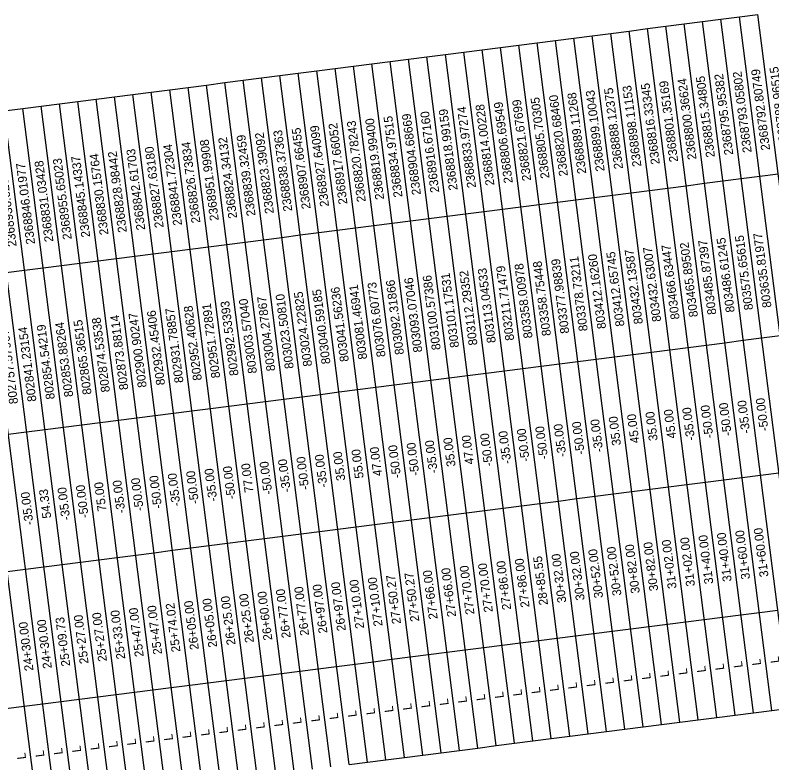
# Model space of a CAD drawing. Extents: x 2364621 to 2374814, y 792603 to 806745.
# Drawn here: x 2368280 to 2370303, y 801237 to 803235 of the extents above; entities that cross this region are included whole.
import ezdxf

# ---------------------------------------------------------------- set-up
doc = ezdxf.new("R2010")
doc.units = 0
doc.layers.add('CTL Sheet Table Cell', color=7, linetype='Continuous')
doc.layers.add('CTL Sheet Text', color=7, linetype='Continuous')

msp = doc.modelspace()

# ---------------------------------------------------------------- linework, layer by layer
at = {"layer": 'CTL Sheet Table Cell'}
for p, q in [((2370068.3, 803211.1), (2370117.4, 803217.4)), ((2370117.4, 803217.4), (2370166.5, 803223.7)), ((2370351.6, 801383.6), (2370117.4, 803217.4)), ((2370166.5, 803223.7), (2370215.7, 803229.9)), ((2370400.7, 801389.9), (2370166.5, 803223.7)), ((2370215.7, 803229.9), (2370264.8, 803236.2)), ((2370449.9, 801396.2), (2370215.7, 803229.9)), ((2370499, 801402.5), (2370264.8, 803236.2)), ((2369921, 803192.3), (2369970.1, 803198.6)), ((2369970.1, 803198.6), (2370019.2, 803204.8)), ((2370204.3, 801364.8), (2369970.1, 803198.6)), ((2370019.2, 803204.8), (2370068.3, 803211.1)), ((2370253.4, 801371.1), (2370019.2, 803204.8)), ((2370302.5, 801377.4), (2370068.3, 803211.1)), ((2369773.6, 803173.5), (2369822.7, 803179.7)), ((2369822.7, 803179.7), (2369871.8, 803186)), ((2370056.9, 801346), (2369822.7, 803179.7)), ((2369871.8, 803186), (2369921, 803192.3)), ((2370106, 801352.3), (2369871.8, 803186)), ((2370155.2, 801358.6), (2369921, 803192.3)), ((2369626.2, 803154.7), (2369675.4, 803160.9)), ((2369675.4, 803160.9), (2369724.5, 803167.2)), ((2369909.6, 801327.2), (2369675.4, 803160.9)), ((2369724.5, 803167.2), (2369773.6, 803173.5)), ((2369958.7, 801333.5), (2369724.5, 803167.2)), ((2370007.8, 801339.7), (2369773.6, 803173.5)), ((2369478.9, 803135.8), (2369528, 803142.1)), ((2369528, 803142.1), (2369577.1, 803148.4)), ((2369762.2, 801308.4), (2369528, 803142.1)), ((2369577.1, 803148.4), (2369626.2, 803154.7)), ((2369811.3, 801314.6), (2369577.1, 803148.4)), ((2369860.5, 801320.9), (2369626.2, 803154.7)), ((2369282.4, 803110.7), (2369331.5, 803117)), ((2369331.5, 803117), (2369380.7, 803123.3)), ((2369565.7, 801283.3), (2369331.5, 803117)), ((2369380.7, 803123.3), (2369429.8, 803129.6)), ((2369614.9, 801289.5), (2369380.7, 803123.3)), ((2369429.8, 803129.6), (2369478.9, 803135.8)), ((2369664, 801295.8), (2369429.8, 803129.6)), ((2369713.1, 801302.1), (2369478.9, 803135.8)), ((2369135.1, 803091.9), (2369184.2, 803098.2)), ((2369184.2, 803098.2), (2369233.3, 803104.5)), ((2369418.4, 801264.5), (2369184.2, 803098.2)), ((2369233.3, 803104.5), (2369282.4, 803110.7)), ((2369467.5, 801270.7), (2369233.3, 803104.5)), ((2369516.6, 801277), (2369282.4, 803110.7)), ((2368987.7, 803073.1), (2369036.8, 803079.4)), ((2369036.8, 803079.4), (2369086, 803085.6)), ((2369271, 801245.6), (2369036.8, 803079.4)), ((2369086, 803085.6), (2369135.1, 803091.9)), ((2369320.2, 801251.9), (2369086, 803085.6)), ((2369369.3, 801258.2), (2369135.1, 803091.9)), ((2368840.4, 803054.3), (2368889.5, 803060.6)), ((2368889.5, 803060.6), (2368938.6, 803066.8)), ((2369123.7, 801226.8), (2368889.5, 803060.6)), ((2368938.6, 803066.8), (2368987.7, 803073.1)), ((2369172.8, 801233.1), (2368938.6, 803066.8)), ((2369221.9, 801239.4), (2368987.7, 803073.1)), ((2368643.9, 803029.2), (2368693, 803035.5)), ((2368693, 803035.5), (2368742.1, 803041.7)), ((2368927.2, 801201.7), (2368693, 803035.5)), ((2368742.1, 803041.7), (2368791.2, 803048)), ((2368976.3, 801208), (2368742.1, 803041.7)), ((2368791.2, 803048), (2368840.4, 803054.3)), ((2369025.4, 801214.3), (2368791.2, 803048)), ((2369074.6, 801220.5), (2368840.4, 803054.3)), ((2368496.5, 803010.4), (2368545.7, 803016.6)), ((2368545.7, 803016.6), (2368594.8, 803022.9)), ((2368779.9, 801182.9), (2368545.7, 803016.6)), ((2368594.8, 803022.9), (2368643.9, 803029.2)), ((2368829, 801189.2), (2368594.8, 803022.9)), ((2368878.1, 801195.4), (2368643.9, 803029.2)), ((2368349.2, 802991.5), (2368398.3, 802997.8)), ((2368398.3, 802997.8), (2368447.4, 803004.1)), ((2368632.5, 801164.1), (2368398.3, 802997.8)), ((2368447.4, 803004.1), (2368496.5, 803010.4)), ((2368681.6, 801170.4), (2368447.4, 803004.1)), ((2368730.7, 801176.6), (2368496.5, 803010.4)), ((2368250.9, 802979), (2368300.1, 802985.3)), ((2368485.1, 801145.3), (2368250.9, 802979)), ((2368300.1, 802985.3), (2368349.2, 802991.5)), ((2368534.3, 801151.5), (2368300.1, 802985.3)), ((2368583.4, 801157.8), (2368349.2, 802991.5)), ((2368337.8, 801126.4), (2368103.6, 802960.2)), ((2368386.9, 801132.7), (2368152.7, 802966.5)), ((2368436, 801139), (2368201.8, 802972.7)), ((2370171.8, 802791.7), (2370220.9, 802798)), ((2370220.9, 802798), (2370270, 802804.2)), ((2370270, 802804.2), (2370319.1, 802810.5)), ((2369975.3, 802766.6), (2370024.4, 802772.9)), ((2370024.4, 802772.9), (2370073.6, 802779.1)), ((2370073.6, 802779.1), (2370122.7, 802785.4)), ((2370122.7, 802785.4), (2370171.8, 802791.7)), ((2369828, 802747.8), (2369877.1, 802754.1)), ((2369877.1, 802754.1), (2369926.2, 802760.3)), ((2369926.2, 802760.3), (2369975.3, 802766.6)), ((2369680.6, 802729), (2369729.7, 802735.2)), ((2369729.7, 802735.2), (2369778.9, 802741.5)), ((2369778.9, 802741.5), (2369828, 802747.8)), ((2369533.3, 802710.1), (2369582.4, 802716.4)), ((2369582.4, 802716.4), (2369631.5, 802722.7)), ((2369631.5, 802722.7), (2369680.6, 802729)), ((2369336.8, 802685), (2369385.9, 802691.3)), ((2369385.9, 802691.3), (2369435, 802697.6)), ((2369435, 802697.6), (2369484.1, 802703.9)), ((2369484.1, 802703.9), (2369533.3, 802710.1)), ((2369189.4, 802666.2), (2369238.6, 802672.5)), ((2369238.6, 802672.5), (2369287.7, 802678.8)), ((2369287.7, 802678.8), (2369336.8, 802685)), ((2369042.1, 802647.4), (2369091.2, 802653.7)), ((2369091.2, 802653.7), (2369140.3, 802660)), ((2369140.3, 802660), (2369189.4, 802666.2)), ((2368894.7, 802628.6), (2368943.8, 802634.9)), ((2368943.8, 802634.9), (2368993, 802641.1)), ((2368993, 802641.1), (2369042.1, 802647.4)), ((2368747.4, 802609.8), (2368796.5, 802616)), ((2368796.5, 802616), (2368845.6, 802622.3)), ((2368845.6, 802622.3), (2368894.7, 802628.6)), ((2368550.9, 802584.7), (2368600, 802591)), ((2368600, 802591), (2368649.1, 802597.2)), ((2368649.1, 802597.2), (2368698.3, 802603.5)), ((2368698.3, 802603.5), (2368747.4, 802609.8)), ((2368403.6, 802565.9), (2368452.7, 802572.1)), ((2368452.7, 802572.1), (2368501.8, 802578.4)), ((2368501.8, 802578.4), (2368550.9, 802584.7)), ((2368256.2, 802547), (2368305.3, 802553.3)), ((2368305.3, 802553.3), (2368354.4, 802559.6)), ((2368354.4, 802559.6), (2368403.6, 802565.9)), ((2370226.2, 802366), (2370275.3, 802372.3)), ((2370275.3, 802372.3), (2370324.4, 802378.6)), ((2370078.8, 802347.2), (2370127.9, 802353.5)), ((2370127.9, 802353.5), (2370177, 802359.7)), ((2370177, 802359.7), (2370226.2, 802366)), ((2369882.3, 802322.1), (2369931.5, 802328.4)), ((2369931.5, 802328.4), (2369980.6, 802334.6)), ((2369980.6, 802334.6), (2370029.7, 802340.9)), ((2370029.7, 802340.9), (2370078.8, 802347.2)), ((2369735, 802303.3), (2369784.1, 802309.5)), ((2369784.1, 802309.5), (2369833.2, 802315.8)), ((2369833.2, 802315.8), (2369882.3, 802322.1)), ((2369587.6, 802284.5), (2369636.7, 802290.7)), ((2369636.7, 802290.7), (2369685.9, 802297)), ((2369685.9, 802297), (2369735, 802303.3)), ((2369440.3, 802265.6), (2369489.4, 802271.9)), ((2369489.4, 802271.9), (2369538.5, 802278.2)), ((2369538.5, 802278.2), (2369587.6, 802284.5)), ((2369243.8, 802240.5), (2369292.9, 802246.8)), ((2369292.9, 802246.8), (2369342, 802253.1)), ((2369342, 802253.1), (2369391.2, 802259.4)), ((2369391.2, 802259.4), (2369440.3, 802265.6)), ((2369096.5, 802221.7), (2369145.6, 802228)), ((2369145.6, 802228), (2369194.7, 802234.3)), ((2369194.7, 802234.3), (2369243.8, 802240.5)), ((2368949.1, 802202.9), (2368998.2, 802209.2)), ((2368998.2, 802209.2), (2369047.3, 802215.4)), ((2369047.3, 802215.4), (2369096.5, 802221.7)), ((2368801.7, 802184.1), (2368850.9, 802190.4)), ((2368850.9, 802190.4), (2368900, 802196.6)), ((2368900, 802196.6), (2368949.1, 802202.9)), ((2368605.3, 802159), (2368654.4, 802165.3)), ((2368654.4, 802165.3), (2368703.5, 802171.5)), ((2368703.5, 802171.5), (2368752.6, 802177.8)), ((2368752.6, 802177.8), (2368801.7, 802184.1)), ((2368457.9, 802140.2), (2368507, 802146.4)), ((2368507, 802146.4), (2368556.2, 802152.7)), ((2368556.2, 802152.7), (2368605.3, 802159)), ((2368310.6, 802121.3), (2368359.7, 802127.6)), ((2368359.7, 802127.6), (2368408.8, 802133.9)), ((2368408.8, 802133.9), (2368457.9, 802140.2)), ((2368261.4, 802115.1), (2368310.6, 802121.3)), ((2370223.1, 801999.5), (2370272.2, 802005.8)), ((2370272.2, 802005.8), (2370321.3, 802012.1)), ((2370075.7, 801980.7), (2370124.8, 801987)), ((2370124.8, 801987), (2370173.9, 801993.3)), ((2370173.9, 801993.3), (2370223.1, 801999.5)), ((2369928.3, 801961.9), (2369977.5, 801968.2)), ((2369977.5, 801968.2), (2370026.6, 801974.4)), ((2370026.6, 801974.4), (2370075.7, 801980.7)), ((2369731.9, 801936.8), (2369781, 801943.1)), ((2369781, 801943.1), (2369830.1, 801949.3)), ((2369830.1, 801949.3), (2369879.2, 801955.6)), ((2369879.2, 801955.6), (2369928.3, 801961.9)), ((2369584.5, 801918), (2369633.6, 801924.3)), ((2369633.6, 801924.3), (2369682.8, 801930.5)), ((2369682.8, 801930.5), (2369731.9, 801936.8)), ((2369437.2, 801899.2), (2369486.3, 801905.4)), ((2369486.3, 801905.4), (2369535.4, 801911.7)), ((2369535.4, 801911.7), (2369584.5, 801918)), ((2369289.8, 801880.3), (2369338.9, 801886.6)), ((2369338.9, 801886.6), (2369388, 801892.9)), ((2369388, 801892.9), (2369437.2, 801899.2)), ((2369142.5, 801861.5), (2369191.6, 801867.8)), ((2369191.6, 801867.8), (2369240.7, 801874.1)), ((2369240.7, 801874.1), (2369289.8, 801880.3)), ((2368946, 801836.4), (2368995.1, 801842.7)), ((2368995.1, 801842.7), (2369044.2, 801849)), ((2369044.2, 801849), (2369093.3, 801855.2)), ((2369093.3, 801855.2), (2369142.5, 801861.5)), ((2368798.6, 801817.6), (2368847.7, 801823.9)), ((2368847.7, 801823.9), (2368896.9, 801830.2)), ((2368896.9, 801830.2), (2368946, 801836.4)), ((2368651.3, 801798.8), (2368700.4, 801805.1)), ((2368700.4, 801805.1), (2368749.5, 801811.3)), ((2368749.5, 801811.3), (2368798.6, 801817.6)), ((2368503.9, 801780), (2368553, 801786.2)), ((2368553, 801786.2), (2368602.2, 801792.5)), ((2368602.2, 801792.5), (2368651.3, 801798.8)), ((2368307.5, 801754.9), (2368356.6, 801761.2)), ((2368356.6, 801761.2), (2368405.7, 801767.4)), ((2368405.7, 801767.4), (2368454.8, 801773.7)), ((2368454.8, 801773.7), (2368503.9, 801780)), ((2368258.3, 801748.6), (2368307.5, 801754.9)), ((2370219.9, 801633.1), (2370269.1, 801639.3)), ((2370269.1, 801639.3), (2370318.2, 801645.6)), ((2370072.6, 801614.2), (2370121.7, 801620.5)), ((2370121.7, 801620.5), (2370170.8, 801626.8)), ((2370170.8, 801626.8), (2370219.9, 801633.1)), ((2369925.2, 801595.4), (2369974.3, 801601.7)), ((2369974.3, 801601.7), (2370023.5, 801608)), ((2370023.5, 801608), (2370072.6, 801614.2)), ((2369777.9, 801576.6), (2369827, 801582.9)), ((2369827, 801582.9), (2369876.1, 801589.2)), ((2369876.1, 801589.2), (2369925.2, 801595.4)), ((2369630.5, 801557.8), (2369679.6, 801564.1)), ((2369679.6, 801564.1), (2369728.8, 801570.3)), ((2369728.8, 801570.3), (2369777.9, 801576.6)), ((2369434, 801532.7), (2369483.2, 801539)), ((2369483.2, 801539), (2369532.3, 801545.2)), ((2369532.3, 801545.2), (2369581.4, 801551.5)), ((2369581.4, 801551.5), (2369630.5, 801557.8)), ((2369286.7, 801513.9), (2369335.8, 801520.1)), ((2369335.8, 801520.1), (2369384.9, 801526.4)), ((2369384.9, 801526.4), (2369434, 801532.7)), ((2369139.3, 801495.1), (2369188.5, 801501.3)), ((2369188.5, 801501.3), (2369237.6, 801507.6)), ((2369237.6, 801507.6), (2369286.7, 801513.9)), ((2368992, 801476.2), (2369041.1, 801482.5)), ((2369041.1, 801482.5), (2369090.2, 801488.8)), ((2369090.2, 801488.8), (2369139.3, 801495.1)), ((2368795.5, 801451.1), (2368844.6, 801457.4)), ((2368844.6, 801457.4), (2368893.8, 801463.7)), ((2368893.8, 801463.7), (2368942.9, 801470)), ((2368942.9, 801470), (2368992, 801476.2)), ((2368648.2, 801432.3), (2368697.3, 801438.6)), ((2368697.3, 801438.6), (2368746.4, 801444.9)), ((2368746.4, 801444.9), (2368795.5, 801451.1)), ((2368500.8, 801413.5), (2368549.9, 801419.8)), ((2368549.9, 801419.8), (2368599, 801426)), ((2368599, 801426), (2368648.2, 801432.3)), ((2368353.5, 801394.7), (2368402.6, 801401)), ((2368402.6, 801401), (2368451.7, 801407.2)), ((2368451.7, 801407.2), (2368500.8, 801413.5)), ((2368255.2, 801382.1), (2368304.3, 801388.4)), ((2368304.3, 801388.4), (2368353.5, 801394.7)), ((2370253.4, 801371.1), (2370302.5, 801377.4)), ((2370302.5, 801377.4), (2370351.6, 801383.6)), ((2370106, 801352.3), (2370155.2, 801358.6)), ((2370155.2, 801358.6), (2370204.3, 801364.8)), ((2370204.3, 801364.8), (2370253.4, 801371.1)), ((2369958.7, 801333.5), (2370007.8, 801339.7)), ((2370007.8, 801339.7), (2370056.9, 801346)), ((2370056.9, 801346), (2370106, 801352.3)), ((2369811.3, 801314.6), (2369860.5, 801320.9)), ((2369860.5, 801320.9), (2369909.6, 801327.2)), ((2369909.6, 801327.2), (2369958.7, 801333.5)), ((2369614.9, 801289.5), (2369664, 801295.8)), ((2369664, 801295.8), (2369713.1, 801302.1)), ((2369713.1, 801302.1), (2369762.2, 801308.4)), ((2369762.2, 801308.4), (2369811.3, 801314.6)), ((2369467.5, 801270.7), (2369516.6, 801277)), ((2369516.6, 801277), (2369565.7, 801283.3)), ((2369565.7, 801283.3), (2369614.9, 801289.5)), ((2369320.2, 801251.9), (2369369.3, 801258.2)), ((2369369.3, 801258.2), (2369418.4, 801264.5)), ((2369418.4, 801264.5), (2369467.5, 801270.7)), ((2369172.8, 801233.1), (2369221.9, 801239.4)), ((2369221.9, 801239.4), (2369271, 801245.6)), ((2369271, 801245.6), (2369320.2, 801251.9))]:
    msp.add_line(p, q, dxfattribs=at)

# ---------------------------------------------------------------- texts
at = {"layer": 'CTL Sheet Text'}
for s, height, p in [('2368788.96515', 23.579, (2370347, 802881)), ('2368795.95382', 23.579, (2370199.6, 802862.2)), ('2368793.05802', 23.579, (2370248.8, 802868.5)), ('2368792.80749', 23.579, (2370297.9, 802874.7)), ('2368801.35169', 23.579, (2370052.3, 802843.4)), ('2368800.36624', 23.579, (2370101.4, 802849.7)), ('2368815.34805', 23.579, (2370150.5, 802855.9)), ('2368888.12375', 23.579, (2369904.9, 802824.6)), ('2368898.11153', 23.579, (2369954, 802830.8)), ('2368816.33345', 23.579, (2370003.2, 802837.1)), ('2368805.70305', 23.579, (2369708.5, 802799.5)), ('2368820.68460', 23.579, (2369757.6, 802805.7)), ('2368889.11268', 23.579, (2369806.7, 802812)), ('2368899.10043', 23.579, (2369855.8, 802818.3)), ('2368814.00228', 23.579, (2369561.1, 802780.7)), ('2368806.69549', 23.579, (2369610.2, 802786.9)), ('2368821.67699', 23.579, (2369659.3, 802793.2)), ('2368916.67160', 23.579, (2369413.7, 802761.8)), ('2368818.99159', 23.579, (2369462.9, 802768.1)), ('2368833.97274', 23.579, (2369512, 802774.4)), ('2368819.99400', 23.579, (2369266.4, 802743)), ('2368834.97515', 23.579, (2369315.5, 802749.3)), ('2368904.68669', 23.579, (2369364.6, 802755.6)), ('2368927.64099', 23.579, (2369119, 802724.2)), ('2368917.66052', 23.579, (2369168.2, 802730.5)), ('2368820.78243', 23.579, (2369217.3, 802736.7)), ('2368839.32459', 23.579, (2368922.6, 802699.1)), ('2368823.39092', 23.579, (2368971.7, 802705.4)), ('2368838.37363', 23.579, (2369020.8, 802711.6)), ('2368907.66455', 23.579, (2369069.9, 802717.9)), ('2368826.73834', 23.579, (2368775.2, 802680.3)), ('2368951.99908', 23.579, (2368824.3, 802686.6)), ('2368824.34132', 23.579, (2368873.5, 802692.8)), ('2368842.61703', 23.579, (2368627.9, 802661.5)), ('2368827.63180', 23.579, (2368677, 802667.7)), ('2368841.72304', 23.579, (2368726.1, 802674)), ('2368845.14337', 23.579, (2368480.5, 802642.6)), ('2368830.15764', 23.579, (2368529.6, 802648.9)), ('2368828.98442', 23.579, (2368578.7, 802655.2)), ('2368936.02031', 23.579, (2368284, 802617.5)), ('2368846.01977', 23.579, (2368333.2, 802623.8)), ('2368831.03428', 23.579, (2368382.3, 802630.1)), ('2368955.65023', 23.579, (2368431.4, 802636.4)), ('803485.87397', 23.579, (2370154.3, 802435.6)), ('803486.61245', 23.579, (2370203.4, 802441.8)), ('803575.65615', 23.579, (2370252.5, 802448.1)), ('803635.81977', 23.579, (2370301.6, 802454.4)), ('803432.63007', 23.579, (2370006.9, 802416.8)), ('803466.63447', 23.579, (2370056.1, 802423)), ('803465.89502', 23.579, (2370105.2, 802429.3)), ('803378.73211', 23.579, (2369810.5, 802391.7)), ('803412.16260', 23.579, (2369859.6, 802397.9)), ('803412.65745', 23.579, (2369908.7, 802404.2)), ('803432.13587', 23.579, (2369957.8, 802410.5)), ('803358.00978', 23.579, (2369663.1, 802372.8)), ('803358.75448', 23.579, (2369712.2, 802379.1)), ('803377.98839', 23.579, (2369761.3, 802385.4)), ('803112.29352', 23.579, (2369515.8, 802354)), ('803113.04533', 23.579, (2369564.9, 802360.3)), ('803211.71479', 23.579, (2369614, 802366.6)), ('803093.07046', 23.579, (2369368.4, 802335.2)), ('803100.57386', 23.579, (2369417.5, 802341.5)), ('803101.17531', 23.579, (2369466.6, 802347.7)), ('803081.46941', 23.579, (2369221, 802316.4)), ('803076.60773', 23.579, (2369270.2, 802322.7)), ('803092.31866', 23.579, (2369319.3, 802328.9)), ('803023.50810', 23.579, (2369024.6, 802291.3)), ('803024.22825', 23.579, (2369073.7, 802297.6)), ('803040.59185', 23.579, (2369122.8, 802303.8)), ('803041.56236', 23.579, (2369171.9, 802310.1)), ('802992.53393', 23.579, (2368877.2, 802272.5)), ('803003.57040', 23.579, (2368926.3, 802278.7)), ('803004.27867', 23.579, (2368975.5, 802285)), ('802931.78857', 23.579, (2368729.9, 802253.6)), ('802952.40628', 23.579, (2368779, 802259.9)), ('802951.72891', 23.579, (2368828.1, 802266.2)), ('802873.88114', 23.579, (2368582.5, 802234.8)), ('802900.90247', 23.579, (2368631.6, 802241.1)), ('802932.45406', 23.579, (2368680.7, 802247.4)), ('802853.88264', 23.579, (2368435.2, 802216)), ('802865.36515', 23.579, (2368484.3, 802222.3)), ('802874.53538', 23.579, (2368533.4, 802228.6)), ('802757.57967', 23.579, (2368287.8, 802197.2)), ('802841.23154', 23.579, (2368336.9, 802203.5)), ('802854.54219', 23.579, (2368386, 802209.7)), ('-50.00', 23.58, (2370293.8, 802124.8)), ('-35.00', 23.58, (2370097.3, 802099.7)), ('-50.00', 23.58, (2370146.5, 802106)), ('-50.00', 23.58, (2370195.6, 802112.2)), ('-35.00', 23.58, (2370244.7, 802118.5)), ('45.00', 23.58, (2369948.5, 802092.5)), ('35.00', 23.58, (2369997.6, 802098.8)), ('45.00', 23.58, (2370046.7, 802105)), ('-50.00', 23.58, (2369802.6, 802062.1)), ('-35.00', 23.58, (2369851.8, 802068.3)), ('35.00', 23.58, (2369899.4, 802086.2)), ('-50.00', 23.58, (2369655.3, 802043.2)), ('-50.00', 23.58, (2369704.4, 802049.5)), ('-35.00', 23.58, (2369753.5, 802055.8)), ('35.00', 23.58, (2369457.3, 802029.7)), ('47.00', 23.58, (2369506.4, 802036)), ('-50.00', 23.58, (2369557, 802030.7)), ('-35.00', 23.58, (2369606.2, 802037)), ('-50.00', 23.58, (2369311.5, 801999.3)), ('-50.00', 23.58, (2369360.6, 802005.6)), ('-35.00', 23.58, (2369409.7, 802011.9)), ('35.00', 23.58, (2369162.6, 801992.1)), ('55.00', 23.58, (2369211.7, 801998.4)), ('47.00', 23.58, (2369260.9, 802004.7)), ('-35.00', 23.58, (2369016.8, 801961.7)), ('-50.00', 23.58, (2369065.9, 801968)), ('-35.00', 23.58, (2369115, 801974.2)), ('-50.00', 23.58, (2368869.4, 801942.9)), ('77.00', 23.58, (2368917, 801960.7)), ('-50.00', 23.58, (2368967.6, 801955.4)), ('-50.00', 23.58, (2368672.9, 801917.8)), ('-35.00', 23.58, (2368722, 801924)), ('-50.00', 23.58, (2368771.2, 801930.3)), ('-35.00', 23.58, (2368820.3, 801936.6)), ('75.00', 23.58, (2368524.1, 801910.6)), ('-35.00', 23.58, (2368574.7, 801905.2)), ('-50.00', 23.58, (2368623.8, 801911.5)), ('54.33', 23.58, (2368376.7, 801891.7)), ('-35.00', 23.58, (2368427.3, 801886.4)), ('-50.00', 23.58, (2368476.5, 801892.7)), ('-35.00', 23.58, (2368329.1, 801873.9)), ('31+60.00', 23.58, (2370293.7, 801735.1)), ('31+40.00', 23.58, (2370146.3, 801716.3)), ('31+40.00', 23.58, (2370195.4, 801722.6)), ('31+60.00', 23.58, (2370244.5, 801728.8)), ('30+82.00', 23.58, (2369999, 801697.5)), ('31+02.00', 23.58, (2370048.1, 801703.7)), ('31+02.00', 23.58, (2370097.2, 801710)), ('30+32.00', 23.58, (2369802.5, 801672.4)), ('30+52.00', 23.58, (2369851.6, 801678.7)), ('30+52.00', 23.58, (2369900.7, 801684.9)), ('30+82.00', 23.58, (2369949.8, 801691.2)), ('27+86.00', 23.58, (2369655.1, 801653.6)), ('28+85.55', 23.58, (2369704.3, 801659.8)), ('30+32.00', 23.58, (2369753.4, 801666.1)), ('27+70.00', 23.58, (2369507.8, 801634.7)), ('27+70.00', 23.58, (2369556.9, 801641)), ('27+86.00', 23.58, (2369606, 801647.3)), ('27+50.27', 23.58, (2369360.4, 801615.9)), ('27+66.00', 23.58, (2369409.5, 801622.2)), ('27+66.00', 23.58, (2369458.7, 801628.5)), ('27+10.00', 23.58, (2369213.1, 801597.1)), ('27+10.00', 23.58, (2369262.2, 801603.4)), ('27+50.27', 23.58, (2369311.3, 801609.6)), ('26+77.00', 23.58, (2369016.6, 801572)), ('26+77.00', 23.58, (2369065.7, 801578.3)), ('26+97.00', 23.58, (2369114.8, 801584.6)), ('26+97.00', 23.58, (2369164, 801590.8)), ('26+25.00', 23.58, (2368869.2, 801553.2)), ('26+25.00', 23.58, (2368918.4, 801559.5)), ('26+60.00', 23.58, (2368967.5, 801565.7)), ('25+74.02', 23.58, (2368721.9, 801534.4)), ('26+05.00', 23.58, (2368771, 801540.6)), ('26+05.00', 23.58, (2368820.1, 801546.9)), ('25+33.00', 23.58, (2368574.5, 801515.5)), ('25+47.00', 23.58, (2368623.7, 801521.8)), ('25+47.00', 23.58, (2368672.8, 801528.1)), ('24+30.00', 23.58, (2368378.1, 801490.5)), ('25+09.73', 23.58, (2368427.2, 801496.7)), ('25+27.00', 23.58, (2368476.3, 801503)), ('25+27.00', 23.58, (2368525.4, 801509.3)), ('24+30.00', 23.58, (2368329, 801484.2)), ('L', 23.6, (2370323, 801505.3)), ('L', 23.6, (2370175.7, 801486.4)), ('L', 23.6, (2370224.8, 801492.7)), ('L', 23.6, (2370273.9, 801499)), ('L', 23.6, (2369979.2, 801461.3)), ('L', 23.6, (2370028.3, 801467.6)), ('L', 23.6, (2370077.4, 801473.9)), ('L', 23.6, (2370126.6, 801480.2)), ('L', 23.6, (2369831.8, 801442.5)), ('L', 23.6, (2369881, 801448.8)), ('L', 23.6, (2369930.1, 801455.1)), ('L', 23.6, (2369684.5, 801423.7)), ('L', 23.6, (2369733.6, 801430)), ('L', 23.6, (2369782.7, 801436.2)), ('L', 23.6, (2369537.1, 801404.9)), ('L', 23.6, (2369586.3, 801411.2)), ('L', 23.6, (2369635.4, 801417.4)), ('L', 23.6, (2369389.8, 801386.1)), ('L', 23.6, (2369438.9, 801392.3)), ('L', 23.6, (2369488, 801398.6)), ('L', 23.6, (2369193.3, 801361)), ('L', 23.6, (2369242.4, 801367.2)), ('L', 23.6, (2369291.5, 801373.5)), ('L', 23.6, (2369340.7, 801379.8)), ('L', 23.6, (2369046, 801342.1)), ('L', 23.6, (2369095.1, 801348.4)), ('L', 23.6, (2369144.2, 801354.7)), ('L', 23.6, (2368898.6, 801323.3)), ('L', 23.6, (2368947.7, 801329.6)), ('L', 23.6, (2368996.8, 801335.9)), ('L', 23.6, (2368751.3, 801304.5)), ('L', 23.6, (2368800.4, 801310.8)), ('L', 23.6, (2368849.5, 801317.1)), ('L', 23.6, (2368554.8, 801279.4)), ('L', 23.6, (2368603.9, 801285.7)), ('L', 23.6, (2368653, 801292)), ('L', 23.6, (2368702.1, 801298.2)), ('L', 23.6, (2368407.4, 801260.6)), ('L', 23.6, (2368456.5, 801266.9)), ('L', 23.6, (2368505.7, 801273.1)), ('L', 23.6, (2368309.2, 801248)), ('L', 23.6, (2368358.3, 801254.3))]:
    msp.add_text(s, height=height, rotation=97.2784, dxfattribs=at).set_placement(p)

doc.saveas('drawing.dxf')
